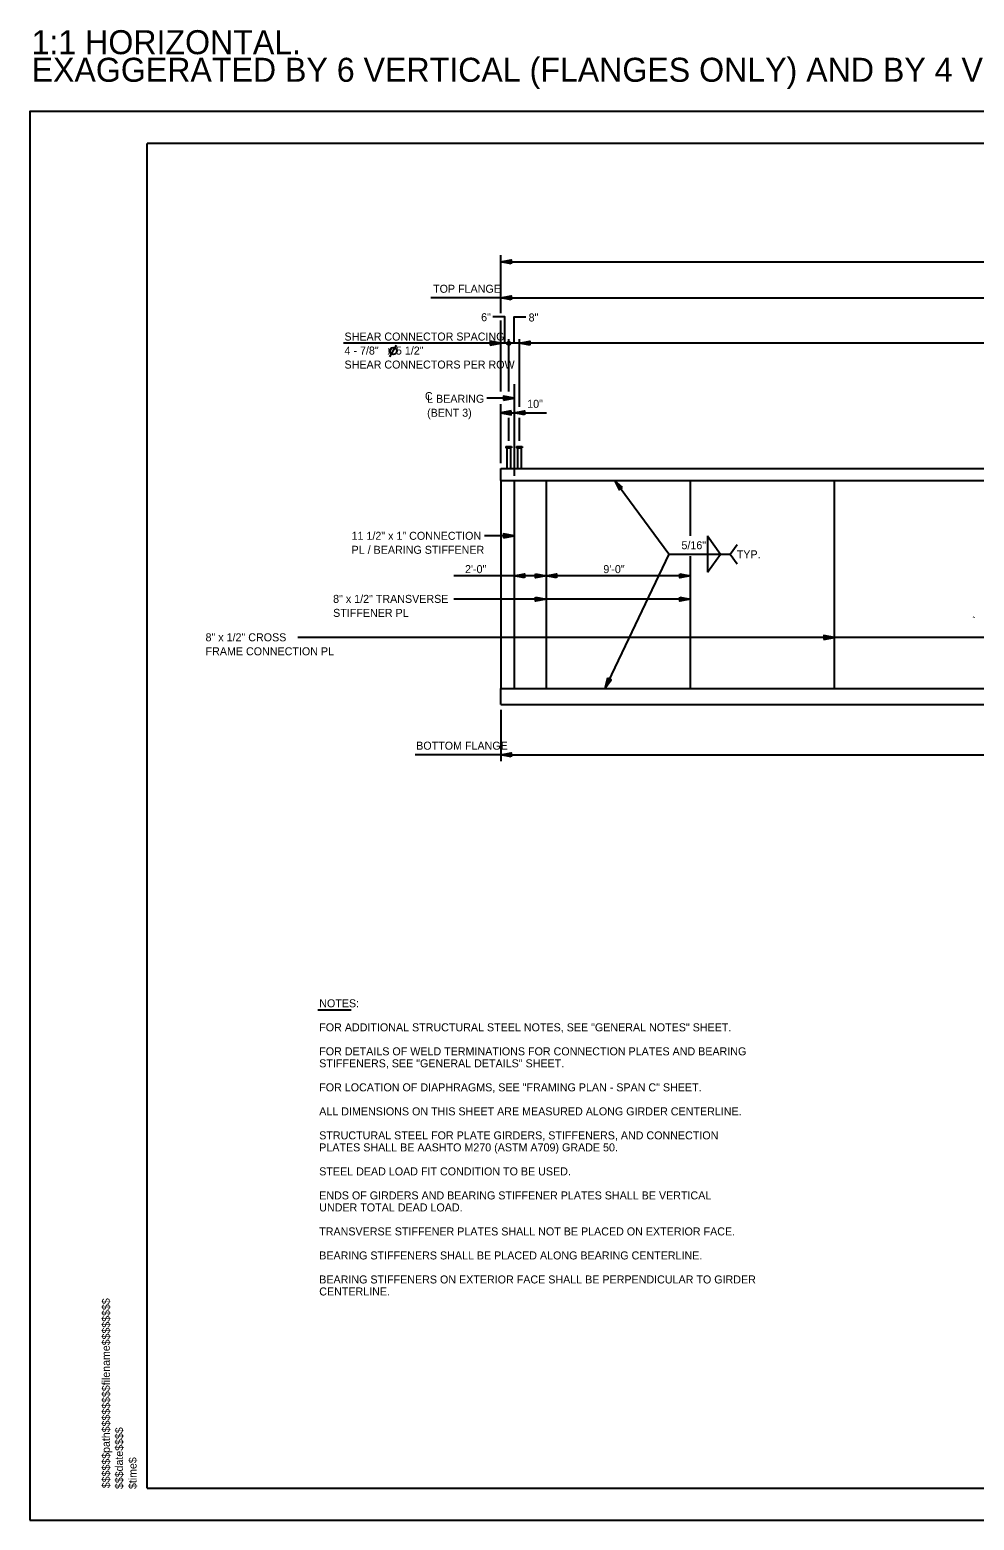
# Model space of a CAD drawing. Extents: x -383 to -161, y -356 to -94.
# Drawn here: x -305.2 to -246.2, y -187.5 to -94.4 of the extents above; entities that cross this region are included whole.
import ezdxf

# ---------------------------------------------------------------- set-up
doc = ezdxf.new("R2010")
doc.units = 0
for name, color, linetype in [('BR_AUTO DIMENSION', 7, 'Continuous'), ('BR_BORDER LINES', 7, 'Continuous'), ('BR_CENTER LINES', 7, 'Continuous'), ('BR_STRUCTURAL STEEL', 7, 'Continuous'), ('BR_TEXT', 7, 'Continuous'), ('Default', 7, 'Continuous'), ('Level 31', 7, 'Continuous'), ('RD_SHT_ID', 7, 'Continuous')]:
    doc.layers.add(name, color=color, linetype=linetype)

msp = doc.modelspace()

# ---------------------------------------------------------------- linework, layer by layer
at = {"layer": 'BR_AUTO DIMENSION'}
for p, q in [((-275.77, -112.096), (-275.77, -108.463)), ((-275.77, -108.876), (-185.922, -108.876)), ((-275.77, -111.134), (-280.14, -111.134)), ((-275.77, -111.134), (-185.922, -111.134)), ((-275.77, -116.993), (-275.77, -112.544)), ((-275.77, -113.971), (-285.586, -113.971)), ((-274.603, -113.971), (-275.77, -113.971)), ((-275.27, -116.993), (-275.27, -113.71)), ((-274.603, -117.94), (-274.603, -113.71)), ((-187.006, -113.971), (-274.603, -113.971)), ((-274.937, -117.397), (-276.639, -117.397)), ((-275.77, -121.468), (-275.77, -117.764)), ((-275.77, -118.321), (-272.918, -118.321)), ((-275.27, -120.06), (-275.27, -118.631)), ((-274.603, -120.06), (-274.603, -118.631)), ((-265.269, -127.138), (-268.658, -122.537)), ((-274.937, -125.99), (-276.785, -125.99)), ((-262.853, -126.005), (-262.853, -128.272)), ((-262.853, -126.005), (-262.048, -127.138)), ((-261.445, -127.138), (-261.012, -126.531)), ((-265.269, -127.138), (-269.266, -135.537)), ((-265.269, -127.138), (-261.445, -127.138)), ((-262.853, -128.272), (-262.048, -127.138)), ((-261.445, -127.138), (-261.012, -127.746)), ((-272.937, -128.508), (-278.695, -128.508)), ((-263.937, -128.508), (-272.937, -128.508)), ((-263.937, -129.95), (-278.695, -129.95)), ((-206.756, -132.351), (-288.443, -132.351)), ((-275.77, -136.871), (-275.77, -140.076)), ((-275.77, -139.676), (-281.117, -139.676)), ((-275.77, -139.676), (-185.922, -139.676)), ((-287.194, -155.612), (-285.117, -155.612))]:
    msp.add_line(p, q, dxfattribs=at)
for points in [[(-275.12, -109.001), (-275.77, -108.876), (-275.12, -108.751)], [(-275.12, -111.259), (-275.77, -111.134), (-275.12, -111.009)], [(-276.42, -114.096), (-275.77, -113.971), (-276.42, -113.846)], [(-273.953, -114.096), (-274.603, -113.971), (-273.953, -113.846)], [(-275.587, -117.522), (-274.937, -117.397), (-275.587, -117.272)], [(-275.12, -118.196), (-275.77, -118.321), (-275.12, -118.446)], [(-274.287, -118.446), (-274.937, -118.321), (-274.287, -118.196)], [(-268.171, -122.987), (-268.658, -122.537), (-268.373, -123.135)], [(-275.587, -126.115), (-274.937, -125.99), (-275.587, -125.865)], [(-274.287, -128.633), (-274.937, -128.508), (-274.287, -128.383)], [(-273.587, -128.383), (-272.937, -128.508), (-273.587, -128.633)], [(-272.287, -128.633), (-272.937, -128.508), (-272.287, -128.383)], [(-264.587, -128.383), (-263.937, -128.508), (-264.587, -128.633)], [(-273.587, -129.825), (-272.937, -129.95), (-273.587, -130.075)], [(-264.587, -129.825), (-263.937, -129.95), (-264.587, -130.075)], [(-255.587, -132.476), (-254.937, -132.351), (-255.587, -132.226)], [(-269.1, -134.897), (-269.266, -135.537), (-268.874, -135.004)], [(-275.12, -139.801), (-275.77, -139.676), (-275.12, -139.551)]]:
    msp.add_lwpolyline(points, close=True, dxfattribs=at)
for points in [[(-275.52, -113.971), (-275.52, -112.325), (-276.26, -112.325)], [(-274.937, -113.971), (-274.937, -112.325), (-274.197, -112.325)]]:
    msp.add_lwpolyline(points, dxfattribs=at)
msp.add_circle((-275.27, -113.971), 0.111, dxfattribs=at)
at = {"layer": 'BR_BORDER LINES'}
for p, q in [((-163.178, -101.489), (-297.843, -101.489)), ((-297.843, -185.489), (-297.843, -101.489)), ((-297.843, -185.489), (-163.178, -185.489))]:
    msp.add_line(p, q, dxfattribs=at)
at = {"layer": 'BR_CENTER LINES'}
msp.add_line((-274.937, -116.535), (-274.937, -122.256), dxfattribs=at)
at = {"layer": 'BR_STRUCTURAL STEEL'}
for p, q in [((-275.77, -122.537), (-275.77, -121.787)), ((-275.77, -121.787), (-185.922, -121.787)), ((-275.77, -122.537), (-185.922, -122.537)), ((-275.77, -122.537), (-275.77, -135.537)), ((-274.937, -122.537), (-274.937, -135.537)), ((-272.937, -122.537), (-272.937, -135.537)), ((-263.937, -122.537), (-263.937, -126.005)), ((-254.937, -122.537), (-254.937, -135.537)), ((-263.937, -127.273), (-263.937, -135.537)), ((-275.77, -135.537), (-185.922, -135.537)), ((-275.77, -136.537), (-275.77, -135.537)), ((-275.77, -136.537), (-185.922, -136.537))]:
    msp.add_line(p, q, dxfattribs=at)
at = {"layer": 'BR_TEXT'}
for p, q in [((-282.694, -114.817), (-282.274, -114.089)), ((-246.23, -131.103), (-246.2, -131.057))]:
    msp.add_line(p, q, dxfattribs=at)
msp.add_circle((-282.484, -114.453), 0.22, dxfattribs=at)
at = {"layer": 'Default'}
for p, q in [((-275.442, -120.412), (-275.442, -120.506)), ((-275.442, -120.412), (-275.098, -120.412)), ((-275.442, -120.506), (-275.098, -120.506)), ((-275.379, -120.506), (-275.379, -121.787)), ((-275.161, -120.506), (-275.161, -121.787)), ((-275.098, -120.412), (-275.098, -120.506)), ((-274.775, -120.412), (-274.775, -120.506)), ((-274.775, -120.412), (-274.431, -120.412)), ((-274.775, -120.506), (-274.431, -120.506)), ((-274.713, -120.506), (-274.713, -121.787)), ((-274.494, -120.506), (-274.494, -121.787)), ((-274.431, -120.412), (-274.431, -120.506))]:
    msp.add_line(p, q, dxfattribs=at)
at = {"layer": 'Level 31'}
msp.add_lwpolyline([(-305.176, -187.489), (-161.176, -187.489), (-161.176, -99.489), (-305.176, -99.489)], close=True, dxfattribs=at)

# ---------------------------------------------------------------- texts
at = {"layer": 'BR_AUTO DIMENSION'}
for s, p in [('TOP FLANGE', (-279.992, -110.815)), ('6"', (-276.992, -112.593)), ('8"', (-274.026, -112.609)), ('10"', (-274.115, -118.002)), ('5/16"', (-264.481, -126.838)), ('TYP.', (-261.028, -127.405)), ('2\'-0"', (-277.998, -128.329)), ('9\'-0"', (-269.359, -128.329)), ('BOTTOM FLANGE', (-281.046, -139.357)), ('NOTES:', (-287.102, -155.451)), ('FOR ADDITIONAL STRUCTURAL STEEL NOTES, SEE "GENERAL NOTES" SHEET.', (-287.102, -156.951)), ('FOR DETAILS OF WELD TERMINATIONS FOR CONNECTION PLATES AND BEARING ', (-287.102, -158.451)), ('STIFFENERS, SEE "GENERAL DETAILS" SHEET.', (-287.102, -159.201)), ('FOR LOCATION OF DIAPHRAGMS, SEE "FRAMING PLAN - SPAN C" SHEET.', (-287.102, -160.701)), ('ALL DIMENSIONS ON THIS SHEET ARE MEASURED ALONG GIRDER CENTERLINE.', (-287.102, -162.201)), ('STRUCTURAL STEEL FOR PLATE GIRDERS, STIFFENERS, AND CONNECTION ', (-287.102, -163.701)), ('PLATES SHALL BE AASHTO M270 (ASTM A709) GRADE 50.', (-287.102, -164.451)), ('STEEL DEAD LOAD FIT CONDITION TO BE USED.', (-287.102, -165.951)), ('ENDS OF GIRDERS AND BEARING STIFFENER PLATES SHALL BE VERTICAL', (-287.102, -167.451)), ('UNDER TOTAL DEAD LOAD.', (-287.102, -168.201)), ('TRANSVERSE STIFFENER PLATES SHALL NOT BE PLACED ON EXTERIOR FACE.', (-287.102, -169.701)), ('BEARING STIFFENERS SHALL BE PLACED ALONG BEARING CENTERLINE.', (-287.102, -171.201)), ('BEARING STIFFENERS ON EXTERIOR FACE SHALL BE PERPENDICULAR TO GIRDER', (-287.102, -172.701)), ('CENTERLINE.', (-287.102, -173.451))]:
    msp.add_text(s, height=0.5, rotation=360, dxfattribs=at).set_placement(p)
at = {"layer": 'BR_TEXT'}
for s, p in [('1:1 HORIZONTAL.', (-305.065, -95.912)), ('EXAGGERATED BY 6 VERTICAL (FLANGES ONLY) AND BY 4 VERTICAL (WEB ONLY).', (-305.065, -97.636))]:
    msp.add_text(s, height=1.5, dxfattribs=at).set_placement(p)
for s, p in [('SHEAR CONNECTOR SPACING', (-285.523, -113.801)), ('4 - 7/8"   x 5 1/2" ', (-285.523, -114.676)), ('SHEAR CONNECTORS PER ROW', (-285.523, -115.551)), ('C', (-280.5, -117.52)), ('L BEARING', (-280.365, -117.686)), ('(BENT 3)', (-280.365, -118.561)), ('11 1/2" x 1" CONNECTION ', (-285.082, -126.247)), ('PL / BEARING STIFFENER', (-285.082, -127.122)), ('8" x 1/2" TRANSVERSE ', (-286.234, -130.187)), ('STIFFENER PL', (-286.234, -131.062)), ('8" x 1/2" CROSS ', (-294.201, -132.588)), ('FRAME CONNECTION PL', (-294.201, -133.463))]:
    msp.add_text(s, height=0.5, rotation=360, dxfattribs=at).set_placement(p)
at = {"layer": 'RD_SHT_ID'}
for s, height, p in [('$$$$$$path$$$$$$$$filename$$$$$$$$', 0.49387, (-300.176, -185.489)), ('$$$date$$$$', 0.49387, (-299.353, -185.542)), ('$time$', 0.4939, (-298.509, -185.542))]:
    msp.add_text(s, height=height, rotation=90, dxfattribs=at).set_placement(p)

doc.saveas('drawing.dxf')
